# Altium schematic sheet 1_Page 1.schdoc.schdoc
size 431 x 309 mm; Designator: FRAME; Symbol: Sheet-Symbol_A4; Device: Sheet-Symbol_A4; Company: Vincent Alfred B. Tomas; Version: V1.0; Page Size: A3; @Project Name: 2023_11_18_PowerTrack; @Page Count: 1; @Update Date: 2024-03-10; @Create Date: 2023-11-18; @Schematic Name: PowerTrack Arduino Shield; Part Number: JLCPCB-002; @Page No: 1; @Page Name: Page 1
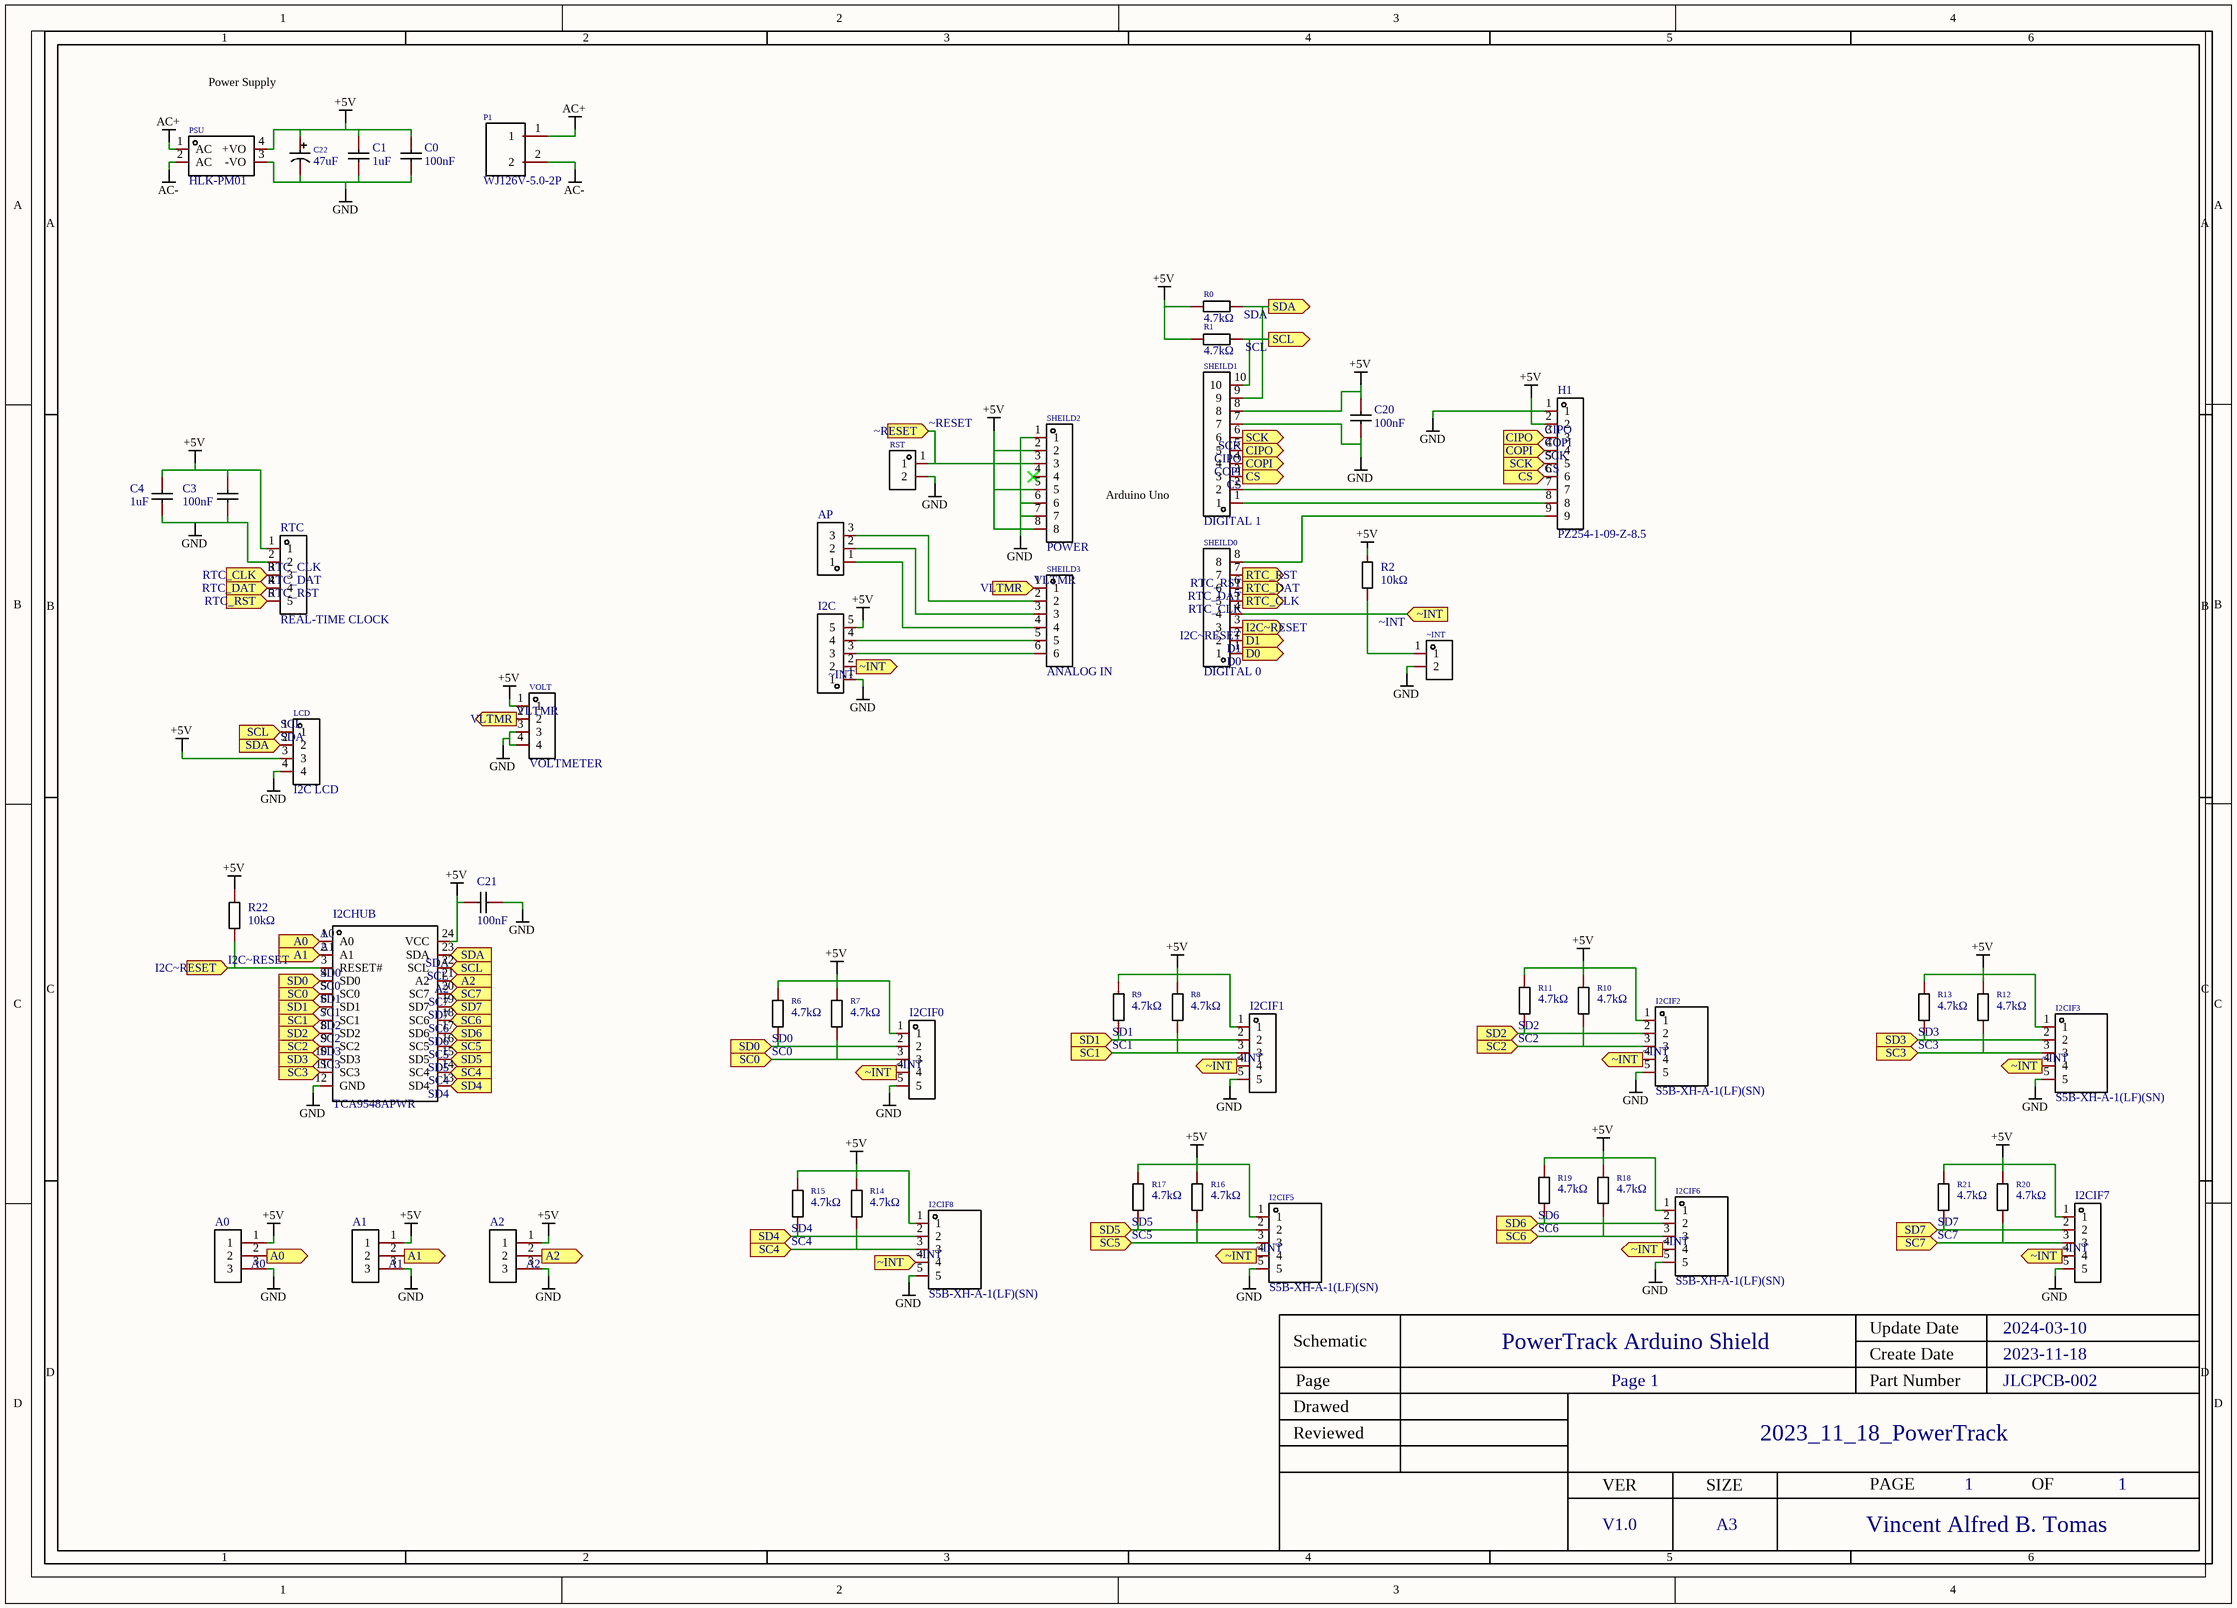
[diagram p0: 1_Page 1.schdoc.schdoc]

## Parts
A0  Solder Switch  [Solder Switch]  (value not drawn)
A1  Solder Switch  [Solder Switch]  (value not drawn)
A2  Solder Switch  [Solder Switch]  (value not drawn)
AP  PZ254V-11-03P  [HDR-TH_3P-P2.54-V-M]  (value not drawn)
C0  100nF  [C0805]
C1  1uF  [C0805]
C3  100nF  [C0805]
C4  1uF  [C0805]
C20  100nF  [C0805]
C21  100nF  [C0805]
C22  47uF  [CAP-TH_BD5.0-P2.00-D0.8-FD]
H1  PZ254-1-09-Z-8.5  [HDR-TH_9P-P2.54-V-M]
I2C  PZ254V-11-05P  [HDR-TH_5P-P2.54-V-M]  (value not drawn)
I2CHUB  TCA9548APWR  [TSSOP-24_L7.8-W4.4-P0.65-LS6.4-BL]
I2CIF0  REAL-TIME CLOCK  [HDR-TH_5P-P2.54-V-M]  (value not drawn)
I2CIF1  REAL-TIME CLOCK  [HDR-TH_5P-P2.54-V-M]  (value not drawn)
I2CIF2  S5B-XH-A-1(LF)(SN)  [CONN-TH_S5B-XH-A-1-LF-SN]
I2CIF3  S5B-XH-A-1(LF)(SN)  [CONN-TH_S5B-XH-A-1-LF-SN]
I2CIF5  S5B-XH-A-1(LF)(SN)  [CONN-TH_S5B-XH-A-1-LF-SN]
I2CIF6  S5B-XH-A-1(LF)(SN)  [CONN-TH_S5B-XH-A-1-LF-SN]
I2CIF7  REAL-TIME CLOCK  [HDR-TH_5P-P2.54-V-M]  (value not drawn)
I2CIF8  S5B-XH-A-1(LF)(SN)  [CONN-TH_S5B-XH-A-1-LF-SN]
LCD  I2C LCD  [HDR-TH_4P-P2.54-V-M]
P1  WJ126V-5.0-2P  [CONN-TH_WJ126V-5.0-2P]
PSU  HLK-PM01  [PWRM-TH_HLK-PM01]
R0  4.7kΩ  [R0805]
R1  4.7kΩ  [R0805]
R2  10kΩ  [R0805]
R6  4.7kΩ  [R0805]
R7  4.7kΩ  [R0805]
R8  4.7kΩ  [R0805]
R9  4.7kΩ  [R0805]
R10  4.7kΩ  [R0805]
R11  4.7kΩ  [R0805]
R12  4.7kΩ  [R0805]
R13  4.7kΩ  [R0805]
R14  4.7kΩ  [R0805]
R15  4.7kΩ  [R0805]
R16  4.7kΩ  [R0805]
R17  4.7kΩ  [R0805]
R18  4.7kΩ  [R0805]
R19  4.7kΩ  [R0805]
R20  4.7kΩ  [R0805]
R21  4.7kΩ  [R0805]
R22  10kΩ  [R0805]
RST  PZ254V-11-02P  [HDR-TH_2P-P2.54-V-M]  (value not drawn)
RTC  REAL-TIME CLOCK  [HDR-TH_5P-P2.54-V-M]
SHEILD0  DIGITAL 0  [HDR-TH_8P-P2.54-V-M]
SHEILD1  DIGITAL 1  [HDR-TH_10P-P2.54-V-M]
SHEILD2  POWER  [HDR-TH_8P-P2.54-V-M]
SHEILD3  ANALOG IN  [HDR-TH_6P-P2.54-V-M]
VOLT  VOLTMETER  [HDR-TH_4P-P2.54-V-M]
~INT  PZ254V-11-02P  [HDR-TH_2P-P2.54-V-M]  (value not drawn)

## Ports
A0 (in), A0 (out), A1 (in), A1 (out), A2 (in), A2 (out), CIPO (in), CIPO (out), COPI (in), COPI (out), CS (in), CS (out), D0 (out), D1 (out), I2C~RESET (in), I2C~RESET (out), RTC_CLK (in), RTC_CLK (out), RTC_DAT (in), RTC_DAT (out), RTC_RST (in), RTC_RST (out), SC0 (in), SC1 (in), SC2 (in), SC3 (in), SC4 (in), SC5 (in), SC6 (in), SC7 (in), SCK (in), SCK (out), SCL (in), SCL (out), SD0 (in), SD1 (in), SD2 (in), SD3 (in), SD4 (in), SD5 (in), SD6 (in), SD7 (in), SDA (in), SDA (out), VLTMR (in), VLTMR (out), ~INT (in), ~INT (out), ~RESET (in)

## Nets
+5V: A0.1 A1.1 A2.1 C0.1 C1.1 C3.1 C4.1 C20.1 C21.1 C22.1 H1.2 I2C.5 I2CHUB.24(VCC) I2CIF0.1 I2CIF1.1 I2CIF2.1 I2CIF3.1 I2CIF5.1 I2CIF6.1 I2CIF7.1 I2CIF8.1 LCD.3 PSU.4(+VO) R0.1 R1.1 R2.2 R6.2 R7.2 R8.2 R9.2 R10.2 R11.2 R12.2 R13.2 R14.2 R15.2 R16.2 R17.2 R18.2 R19.2 R20.2 R21.2 R22.2 RTC.1 SHEILD1.8 SHEILD2.2 SHEILD2.5 SHEILD2.8 VOLT.1
AC+: P1.1 PSU.1(AC)
AC-: P1.2 PSU.2(AC)
GND: A0.3 A1.3 A2.3 C0.2 C1.2 C3.2 C4.2 C20.2 C21.2 C22.2 H1.1 I2C.1 I2CHUB.12(GND) I2CIF0.5 I2CIF1.5 I2CIF2.5 I2CIF3.5 I2CIF5.5 I2CIF6.5 I2CIF7.5 I2CIF8.5 LCD.4 PSU.3(-VO) RST.2 RTC.2 SHEILD1.7 SHEILD2.1 SHEILD2.6 SHEILD2.7 VOLT.3 VOLT.4 ~INT.2
A0: A0.2 I2CHUB.1(A0) ; port A0
A1: A1.2 I2CHUB.2(A1) ; port A1
A2: A2.2 I2CHUB.21(A2) ; port A2
CIPO: H1.3 SHEILD1.5 ; port CIPO
COPI: H1.4 SHEILD1.4 ; port COPI
CS: H1.6 SHEILD1.3 ; port CS
D0: SHEILD0.1 ; port D0
D1: SHEILD0.2 ; port D1
I2C~RESET: I2CHUB.3(RESET#) R22.1 SHEILD0.3 ; port I2C~RESET
RTC_CLK: RTC.3 SHEILD0.5 ; port RTC_CLK
RTC_DAT: RTC.4 SHEILD0.6 ; port RTC_DAT
RTC_RST: RTC.5 SHEILD0.7 ; port RTC_RST
SC0: I2CHUB.5(SC0) I2CIF0.3 R7.1 ; port SC0
SC1: I2CHUB.7(SC1) I2CIF1.3 R8.1 ; port SC1
SC2: I2CHUB.9(SC2) I2CIF2.3 R10.1 ; port SC2
SC3: I2CHUB.11(SC3) I2CIF3.3 R12.1 ; port SC3
SC4: I2CHUB.14(SC4) I2CIF8.3 R14.1 ; port SC4
SC5: I2CHUB.16(SC5) I2CIF5.3 R16.1 ; port SC5
SC6: I2CHUB.18(SC6) I2CIF6.3 R18.1 ; port SC6
SC7: I2CHUB.20(SC7) I2CIF7.3 R20.1 ; port SC7
SCK: H1.5 SHEILD1.6 ; port SCK
SCL: I2CHUB.22(SCL) LCD.1 R1.2 SHEILD1.10 ; port SCL
SD0: I2CHUB.4(SD0) I2CIF0.2 R6.1 ; port SD0
SD1: I2CHUB.6(SD1) I2CIF1.2 R9.1 ; port SD1
SD2: I2CHUB.8(SD2) I2CIF2.2 R11.1 ; port SD2
SD3: I2CHUB.10(SD3) I2CIF3.2 R13.1 ; port SD3
SD4: I2CHUB.13(SD4) I2CIF8.2 R15.1 ; port SD4
SD5: I2CHUB.15(SD5) I2CIF5.2 R17.1 ; port SD5
SD6: I2CHUB.17(SD6) I2CIF6.2 R19.1 ; port SD6
SD7: I2CHUB.19(SD7) I2CIF7.2 R21.1 ; port SD7
SDA: I2CHUB.23(SDA) LCD.2 R0.2 SHEILD1.9 ; port SDA
VLTMR: SHEILD3.1 VOLT.2 ; port VLTMR
~INT: I2C.2 I2CIF0.4 I2CIF1.4 I2CIF2.4 I2CIF3.4 I2CIF5.4 I2CIF6.4 I2CIF7.4 I2CIF8.4 R2.1 SHEILD0.4 ~INT.1 ; port ~INT
~RESET: RST.1 SHEILD2.3 ; port ~RESET
NetAP_1: AP.1 SHEILD3.4
NetAP_2: AP.2 SHEILD3.3
NetAP_3: AP.3 SHEILD3.2
NetH1_7: H1.7 SHEILD1.2
NetH1_8: H1.8 SHEILD1.1
NetH1_9: H1.9 SHEILD0.8
NetI2C_3: I2C.3 SHEILD3.6
NetI2C_4: I2C.4 SHEILD3.5

Not connected (* = marked no-connect by the designer): SHEILD2 4*

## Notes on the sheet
- Power Supply
- Arduino Uno

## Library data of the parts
A0-A2 = Solder Switch: Add into BOM: yes
AP = PZ254V-11-03P: Manufacturer: XFCN(兴飞); Symbol: PZ254V-11-03P_C2937625; Add into BOM: yes; Pin Structure: 1x3P; Pitch: 2.54mm; Circluar Pins/Square Pins: Square Pins; Current Rating (Max): 3A; Voltage Rating (Max): 250V; Description: Pin Structure:1x3P Pitch:2.54mm Row Spacing:- Circluar Pins/Square Pins:Square Pins Mounting Type:Straight Number of Rows:Plugin Number of Pins:3P Current Rating (Max):3A Voltage Rating (Max):250V Length of Mating Pin:6mm Insulation Height:2.5mm Length of
C0 C3 C20 C21 = CL21B104KBCNNNC: Capacitance: Tolerance:±10% Tolerance:±10% Voltage Rated: Temperature Coefficient:; Manufacturer: SAMSUNG(三星); Add into BOM: yes; Tolerance: ±10%
C1 C4 = CL21B105KBFNNNE: Capacitance: Tolerance:±10% Tolerance:±10% Voltage Rated: Temperature Coefficient:; Manufacturer: SAMSUNG(三星); Add into BOM: yes; Tolerance: ±10%
C22 = KS476M025D07RR0VH2FP0: Manufacturer: CX(承兴); Symbol: 47uF 25V 5*7; Add into BOM: yes; Tolerance: ±20%; Lifetime @ Temp: 1000hrs@105℃; Description: Capacitance:47uF Tolerance:±20% Tolerance:±20% Rated Voltage: Lead Spacing: φD: L: Lifetime @ Temp:1000hrs@105℃ Operating Temperature:-40℃~+105℃ Operating Temperature:-40℃~+105℃
H1 = PZ254-1-09-Z-8.5: Manufacturer: HCTL(华灿天禄); Add into BOM: yes; Pin Structure: 1x9P; Pitch: 2.54mm; Circluar Pins/Square Pins: Square Pins; Current Rating (Max): 3A; Soldering Temperature(Max): 260℃@10S; Description: Pin Structure:1x9P Pitch:2.54mm Row Spacing:- Circluar Pins/Square Pins:Square Pins Mounting Type:Straight Number of Rows:Plugin Number of Pins:9P Current Rating (Max):3A Voltage Rating (Max):- Length of Mating Pin:6mm Insulation Height:2.5mm Length of En
I2C = PZ254V-11-05P: Manufacturer: XFCN(兴飞); Manufacturer Part: REAL-TIME CLOCK; Add into BOM: yes; Pitch: 2.54mm; Pin Structure: 1x5P; Circluar Pins/Square Pins: Square Pins; Description: Number of Rows:Plugin Number of Pins:5P Pitch:2.54mm Pin Structure:1x5P Row Spacing:- Mounting Type:Straight Circluar Pins/Square Pins:Square Pins Current Rating (Max):- Voltage Rating (Max):- Length of Mating Pin:6mm Insulation Height:2.5mm Length of End
I2CHUB = TCA9548APWR: Manufacturer: TI(德州仪器); Add into BOM: yes
I2CIF0 I2CIF1 I2CIF7 RTC = PZ254V-11-05P: Manufacturer: XFCN(兴飞); Add into BOM: yes; Pitch: 2.54mm; Pin Structure: 1x5P; Circluar Pins/Square Pins: Square Pins; Description: Number of Rows:Plugin Number of Pins:5P Pitch:2.54mm Pin Structure:1x5P Row Spacing:- Mounting Type:Straight Circluar Pins/Square Pins:Square Pins Current Rating (Max):- Voltage Rating (Max):- Length of Mating Pin:6mm Insulation Height:2.5mm Length of End
I2CIF2 I2CIF3 I2CIF5 I2CIF6 I2CIF8 = S5B-XH-A-1(LF)(SN): Manufacturer: JST; Add into BOM: yes; Pins Structure: 1x5P; Pitch: 2.5mm; Reference Series: XH; Number of PINs Per Row: 5; Description: Pins Structure:1x5P Pitch:2.5mm Mounting Style:Right-Angle Reference Series:XH Number of Pins:5P Number of Rows:1 Number of PINs Per Row:5 Row Spacing:- Contact Material:Brass
LCD VOLT = PZ254V-11-04P: Manufacturer: XFCN(兴飞); Symbol: PZ254V-11-04P_C2691448; Add into BOM: yes; Pin Structure: 1x4P; Pitch: 2.54mm; Circluar Pins/Square Pins: Square Pins; Current Rating (Max): 3A; Voltage Rating (Max): 250V; Description: Pin Structure:1x4P Pitch:2.54mm Row Spacing:- Circluar Pins/Square Pins:Square Pins Mounting Type:Straight Number of Rows:Plugin Number of Pins:4P Current Rating (Max):3A Voltage Rating (Max):250V Length of Mating Pin:6mm Insulation Height:2.5mm Length of
P1 = WJ126V-5.0-2P: Manufacturer: KANGNEX(康奈克斯电气); Add into BOM: yes; Pitch: 5mm; Structure: 1x2P; Number of PINs Per Row: 2; Current Rating (Max): 18A; Voltage Rating (Max): 250V; Wire Gauge - AWG: 14~26; Wire Gauge - mm2: 2.5; Description: Pitch:5mm Structure:1x2P Number of Rows:1 Number of PINs Per Row:2 Mounting Style:Straight Current Rating (Max):18A Voltage Rating (Max):250V Wire Gauge - AWG:14~26 Wire Gauge - AWG:14~26 Wire Gauge - mm2:2.5 Wire Gauge - mm2:2.5 Operating Temperature Ran
PSU = HLK-PM01: Manufacturer: HI-LINK(海凌科); Add into BOM: yes; Conversion Type: AC-DC; Function: 降压型; Input Voltage(AC): 90VAC~265VAC; Input Voltage(DC): 120V~350V; Output Voltage: 5V; Output Current (Max): 0.6A; Output Power: 3W; Isolated Or Voltage Regulation: 隔离稳压; Output Channel: 1; Insulated Voltage: 3kV@AC; Conversion Efficiency: 73%; Description: Conversion Type:AC-DC Function:降压型 Input Voltage(AC):90VAC~265VAC Input Voltage(AC):90VAC~265VAC Input Voltage(DC):120V~350V Input Voltage(DC):120V~350V Output Voltage:5V Output Voltage:5V Output Current (Max):0.6A Output Current (Max):0.6A Output Power:3
R0 R1 R6-R21 = 0805W8F4701T5E: Manufacturer: UNI-ROYAL(厚声); Add into BOM: yes; Tolerance: ±1%; Temperature Coefficient: ±100ppm/℃; Description: Type:Thick Film Resistors Resistance:4.7kΩ Tolerance:±1% Tolerance:±1% Power(Watts): Overload Voltage (Max): Temperature Coefficient:±100ppm/℃ Temperature Coefficient:±100ppm/℃ Operating Temperature Range:-55℃~+155℃ Operating Temperature Range:-55℃~+155℃
R2 R22 = 0805W8F1002T5E: Manufacturer: UNI-ROYAL(厚声); Add into BOM: yes; Tolerance: ±1%; Temperature Coefficient: ±100ppm/℃; Description: Resistance:10000Ω Tolerance:±1% Tolerance:±1% Power(Watts): Overload Voltage (Max): Temperature Coefficient:±100ppm/℃ Temperature Coefficient:±100ppm/℃ Type:Thick Film Resistors Operating Temperature Range:-55℃~+155℃ Operating Temperature Range:-55℃~+155℃
RST ~INT = PZ254V-11-02P: Manufacturer: XFCN(兴飞); Add into BOM: yes; Pin Structure: 1x2P; Pitch: 2.54mm; Circluar Pins/Square Pins: Square Pins; Description: Pin Structure:1x2P Pitch:2.54mm Row Spacing:- Circluar Pins/Square Pins:Square Pins Mounting Type:Straight Number of Rows:Plugin Number of Pins:2P Current Rating (Max):- Voltage Rating (Max):- Length of Mating Pin:6mm Insulation Height:2.5mm Length of End
SHEILD0 SHEILD2 = PZ254V-11-08P: Manufacturer: XFCN(兴飞); Add into BOM: yes; Pitch: 2.54mm; Pin Structure: 1x8P; Circluar Pins/Square Pins: Square Pins; Description: Number of Rows:Plugin Number of Pins:8P Pitch:2.54mm Pin Structure:1x8P Row Spacing:- Mounting Type:Straight Circluar Pins/Square Pins:Square Pins Current Rating (Max):- Voltage Rating (Max):- Length of Mating Pin:6mm Insulation Height:2.5mm Length of End
SHEILD1 = X6511WV-10H-C60D30: Manufacturer: XKB Connectivity(中国星坤); Symbol: X6511WV-10H-C30D60; Add into BOM: yes; Pin Structure: 1x10P; Pitch: 2.54mm; Circluar Pins/Square Pins: Square Pins; Current Rating (Max): 3A; Voltage Rating (Max): 250V; Welding Temperature (Max): 260℃; Description: Pin Structure:1x10P Pitch:2.54mm Number of Pins:10P Mounting Type:Straight Number of Rows:Plugin Row Spacing:- Circluar Pins/Square Pins:Square Pins Current Rating (Max):3A Voltage Rating (Max):250V Length of Mating Pin:6mm Insulation Height:2.5mm Length
SHEILD3 = PZ254V-11-06P: Manufacturer: XFCN(兴飞); Add into BOM: yes; Pitch: 2.54mm; Pin Structure: 1x6P; Circluar Pins/Square Pins: Square Pins; Description: Number of Rows:单排 Number of Pins:6 Pitch:2.54mm Pin Structure:1x6P Row Spacing:- Mounting Type:Straight Circluar Pins/Square Pins:Square Pins Current Rating (Max):- Voltage Rating (Max):- Length of Mating Pin:6mm Insulation Height:2.5mm Length of End Conn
